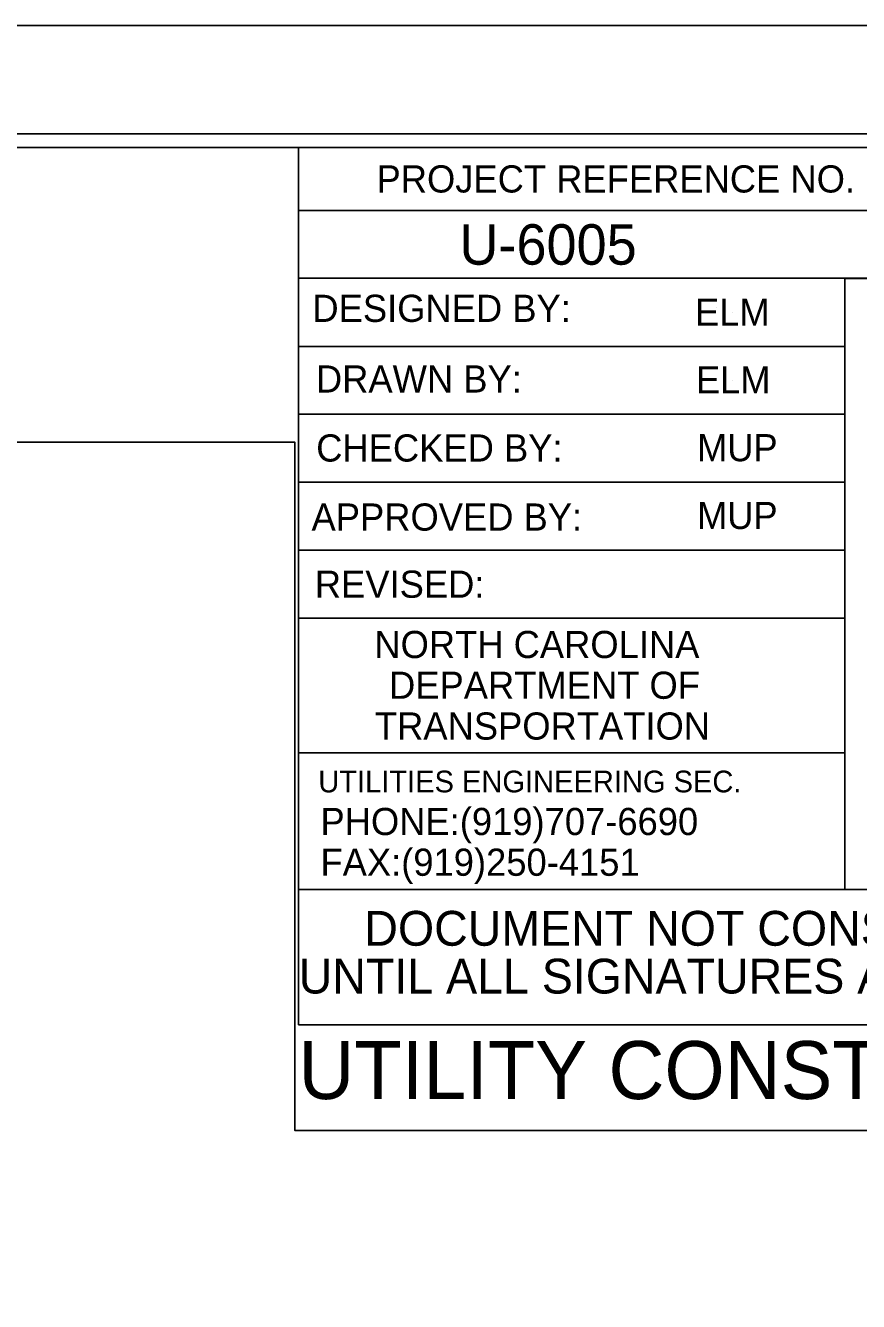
# Model space of a CAD drawing. Extents: x 0 to 2694, y -754 to 1499.
# Drawn here: x 2.388 to 2.644, y 1.4412 to 1.8333 of the extents above; entities that cross this region are included whole.
import ezdxf

# ---------------------------------------------------------------- set-up
doc = ezdxf.new("R2010")
doc.units = 0
for name, color, linetype in [('Scratch_Level_3', 7, 'Continuous'), ('UC Plan Profile Sheet 34 CELL', 7, 'Continuous'), ('UC Plan Sheet 34 CELL', 7, 'Continuous'), ('UE Plan Profile Sheet 34 CELL', 7, 'Continuous')]:
    doc.layers.add(name, color=color, linetype=linetype)

msp = doc.modelspace()

# ---------------------------------------------------------------- linework, layer by layer
at = {"layer": 'Scratch_Level_3'}
msp.add_lwpolyline([(0.39416, 0.90275), (0.39416, 1.70532), (2.47076, 1.70532), (2.47076, 1.49375), (2.76084, 1.49375), (2.76084, 0.90275)], close=True, dxfattribs=at)
at = {"layer": 'UC Plan Profile Sheet 34 CELL'}
for p, q in [((2.60044, 1.74676), (2.60044, 1.74676)), ((2.4719, 1.52621), (2.4719, 1.56775)), ((2.80496, 1.52621), (2.4719, 1.52621))]:
    msp.add_line(p, q, dxfattribs=at)
for points in [[(0.02749, 0.00833), (2.83333, 0.00833), (2.83333, 1.83333), (0.02749, 1.83333)], [(0.04916, 0.04166), (2.82583, 0.04166), (2.82583, 1.8), (0.04916, 1.8)], [(2.80499, 1.79583), (0.30499, 1.79583), (0.30499, 0.04583), (2.80499, 0.04583)]]:
    msp.add_lwpolyline(points, close=True, dxfattribs=at)
at = {"layer": 'UC Plan Sheet 34 CELL'}
for p, q in [((2.4719, 1.77648), (2.80496, 1.77648)), ((2.55581, 1.76604), (2.55581, 1.76604)), ((2.6054, 1.74516), (2.6054, 1.74516)), ((2.4719, 1.7347), (2.63979, 1.7347)), ((2.6054, 1.72427), (2.6054, 1.72427)), ((2.4719, 1.71383), (2.63979, 1.71383)), ((2.6054, 1.70339), (2.6054, 1.70339)), ((2.4719, 1.69295), (2.63979, 1.69295)), ((2.6054, 1.68252), (2.6054, 1.68252)), ((2.4719, 1.67208), (2.63979, 1.67208)), ((2.4719, 1.65118), (2.63979, 1.65118)), ((2.4719, 1.60977), (2.63979, 1.60977))]:
    msp.add_line(p, q, dxfattribs=at)
for points in [[(2.4719, 1.79581), (2.80496, 1.79581), (2.80496, 1.75568)], [(2.80496, 1.75568), (2.4719, 1.75568), (2.4719, 1.79581)], [(2.63979, 1.75568), (2.63979, 1.56775), (2.4719, 1.56775), (2.4719, 1.79581)], [(2.80496, 1.56775), (2.63979, 1.56775), (2.63979, 1.7556), (2.80496, 1.7556)]]:
    msp.add_lwpolyline(points, dxfattribs=at)

# ---------------------------------------------------------------- texts
at = {"layer": 'UC Plan Profile Sheet 34 CELL'}
for s, height, p in [('U-6005', 0.01243, (2.52136, 1.75982)), ('ELM', 0.008333, (2.59379, 1.74103)), ('ELM', 0.008333, (2.59408, 1.72025)), ('MUP', 0.008333, (2.59442, 1.69941)), ('MUP', 0.008333, (2.59442, 1.67858)), ('UTILITY CONSTRUCTION', 0.0178124, (2.4719, 1.50337))]:
    msp.add_text(s, height=height, dxfattribs=at).set_placement(p)
at = {"layer": 'UC Plan Sheet 34 CELL'}
for s, height, p in [('PROJECT REFERENCE NO.', 0.0083524, (2.4959, 1.782)), ('DESIGNED BY:', 0.0083524, (2.47619, 1.74223)), ('DRAWN BY:', 0.008352, (2.47727, 1.72052)), ('CHECKED BY:', 0.0083524, (2.47736, 1.69931)), ('APPROVED BY:', 0.0083524, (2.47592, 1.67808)), ('REVISED:', 0.008352, (2.47694, 1.65745)), ('NORTH CAROLINA', 0.0083524, (2.49523, 1.63891)), ('DEPARTMENT OF', 0.0083524, (2.49975, 1.62639)), ('TRANSPORTATION', 0.0083524, (2.4954, 1.61385)), ('UTILITIES ENGINEERING SEC.', 0.0066819, (2.47799, 1.59763)), ('PHONE:(919)707-6690', 0.0083524, (2.47867, 1.58451)), ('FAX:(919)250-4151', 0.0083524, (2.47867, 1.57199))]:
    msp.add_text(s, height=height, dxfattribs=at).set_placement(p)
at = {"layer": 'UE Plan Profile Sheet 34 CELL'}
for s, p in [('DOCUMENT NOT CONSIDERED FINAL ', (2.49215, 1.5505)), ('UNTIL ALL SIGNATURES ARE COMPLETED', (2.47197, 1.53581))]:
    msp.add_text(s, height=0.010697, dxfattribs=at).set_placement(p)

doc.saveas('drawing.dxf')
